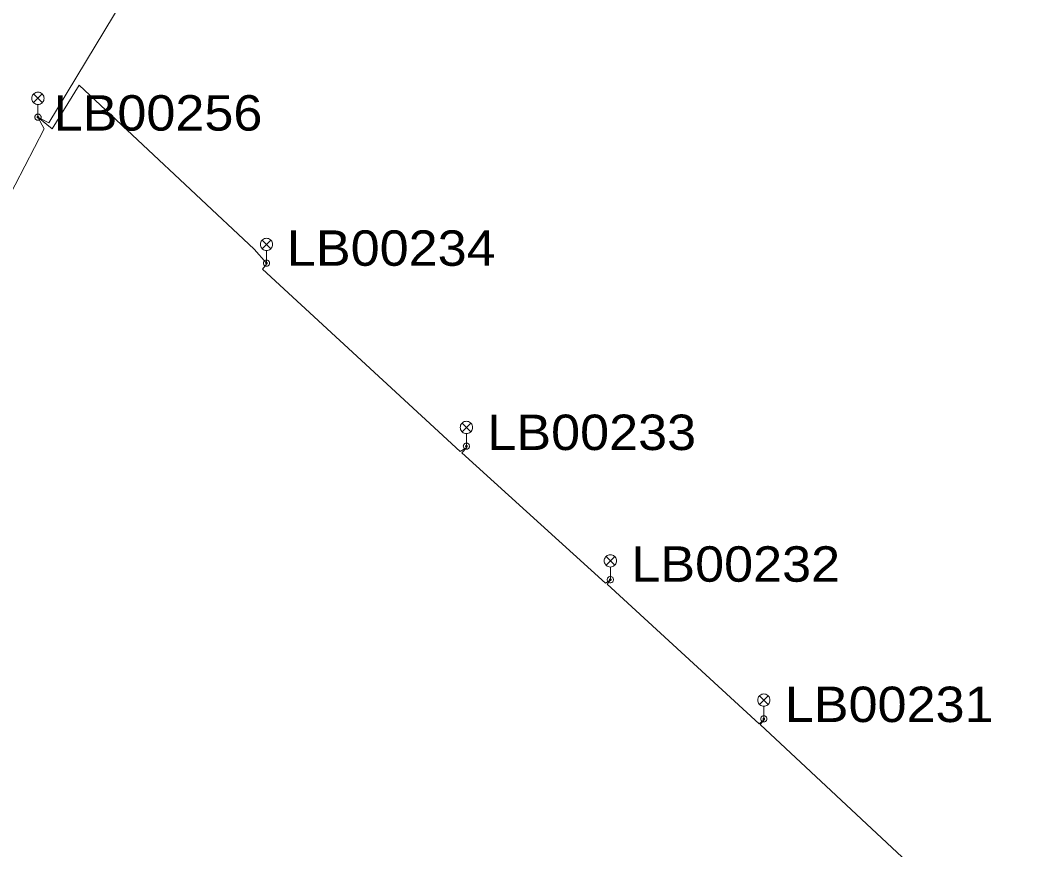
# Model space of a CAD drawing. Extents: x -688049 to -687261, y -973611 to -973038.
# Drawn here: x -687914.5 to -687853.2, y -973537 to -973486.2 of the extents above; entities that cross this region are included whole.
import ezdxf

# ---------------------------------------------------------------- set-up
doc = ezdxf.new("R2010")
doc.units = 0
doc.header["$LTSCALE"] = 0.87
doc.layers.add('1', color=7, linetype='Continuous', lineweight=13)

msp = doc.modelspace()

# ---------------------------------------------------------------- linework, layer by layer
at = {"layer": '1'}
for p, q in [((-687913.655, -973490.735), (-687913.125, -973491.265)), ((-687913.655, -973491.265), (-687913.125, -973490.735)), ((-687913.39, -973492.15), (-687913.39, -973491.375)), ((-687899.685, -973499.665), (-687899.155, -973500.195)), ((-687899.685, -973500.195), (-687899.155, -973499.665)), ((-687899.42, -973501.08), (-687899.42, -973500.305)), ((-687887.465, -973510.855), (-687886.935, -973511.385)), ((-687887.465, -973511.385), (-687886.935, -973510.855)), ((-687887.2, -973512.27), (-687887.2, -973511.495)), ((-687878.665, -973519.015), (-687878.135, -973519.545)), ((-687878.665, -973519.545), (-687878.135, -973519.015)), ((-687878.4, -973520.43), (-687878.4, -973519.655)), ((-687869.285, -973527.525), (-687868.755, -973528.055)), ((-687869.285, -973528.055), (-687868.755, -973527.525)), ((-687869.02, -973528.94), (-687869.02, -973528.165))]:
    msp.add_line(p, q, dxfattribs=at)
for points in [[(-687913.39, -973492.15), (-687912.727, -973492.501), (-687897.443, -973467.178), (-687898.272, -973465.715)], [(-687913.39, -973492.15), (-687912.526, -973492.858), (-687910.875, -973490.203), (-687900.181, -973500.219), (-687899.42, -973501.08)], [(-687942.67, -973532.11), (-687942.806, -973531.57), (-687934.841, -973522.602), (-687917.755, -973502.005), (-687913.006, -973492.864), (-687913.39, -973492.15)], [(-687899.42, -973501.13), (-687899.671, -973501.442), (-687887.585, -973512.602), (-687887.167, -973512.344)], [(-687887.167, -973512.344), (-687887.479, -973512.665), (-687878.69, -973520.633), (-687878.4, -973520.43)], [(-687878.4, -973520.43), (-687878.602, -973520.696), (-687869.304, -973529.25), (-687868.985, -973528.975)], [(-687868.985, -973528.975), (-687869.24, -973529.284), (-687853.757, -973543.759), (-687853.18, -973543.18)]]:
    msp.add_lwpolyline(points, dxfattribs=at)
for points in [[(-687913.015, -973491), (-687913.021, -973490.935), (-687913.038, -973490.872), (-687913.065, -973490.812), (-687913.103, -973490.759), (-687913.149, -973490.713), (-687913.202, -973490.675), (-687913.262, -973490.648), (-687913.325, -973490.631), (-687913.39, -973490.625), (-687913.455, -973490.631), (-687913.518, -973490.648), (-687913.578, -973490.675), (-687913.631, -973490.713), (-687913.677, -973490.759), (-687913.715, -973490.812), (-687913.742, -973490.872), (-687913.759, -973490.935), (-687913.765, -973491), (-687913.759, -973491.065), (-687913.742, -973491.128), (-687913.715, -973491.188), (-687913.677, -973491.241), (-687913.631, -973491.287), (-687913.578, -973491.325), (-687913.518, -973491.352), (-687913.455, -973491.369), (-687913.39, -973491.375), (-687913.325, -973491.369), (-687913.262, -973491.352), (-687913.202, -973491.325), (-687913.149, -973491.287), (-687913.103, -973491.241), (-687913.065, -973491.188), (-687913.038, -973491.128), (-687913.021, -973491.065)], [(-687913.2, -973492.15), (-687913.203, -973492.117), (-687913.211, -973492.085), (-687913.225, -973492.055), (-687913.244, -973492.028), (-687913.268, -973492.004), (-687913.295, -973491.985), (-687913.325, -973491.971), (-687913.357, -973491.963), (-687913.39, -973491.96), (-687913.423, -973491.963), (-687913.455, -973491.971), (-687913.485, -973491.985), (-687913.512, -973492.004), (-687913.536, -973492.028), (-687913.555, -973492.055), (-687913.569, -973492.085), (-687913.577, -973492.117), (-687913.58, -973492.15), (-687913.577, -973492.183), (-687913.569, -973492.215), (-687913.555, -973492.245), (-687913.536, -973492.272), (-687913.512, -973492.296), (-687913.485, -973492.315), (-687913.455, -973492.329), (-687913.423, -973492.337), (-687913.39, -973492.34), (-687913.357, -973492.337), (-687913.325, -973492.329), (-687913.295, -973492.315), (-687913.268, -973492.296), (-687913.244, -973492.272), (-687913.225, -973492.245), (-687913.211, -973492.215), (-687913.203, -973492.183)], [(-687913.34, -973492.15), (-687913.341, -973492.141), (-687913.343, -973492.133), (-687913.347, -973492.125), (-687913.352, -973492.118), (-687913.358, -973492.112), (-687913.365, -973492.107), (-687913.373, -973492.103), (-687913.381, -973492.101), (-687913.39, -973492.1), (-687913.399, -973492.101), (-687913.407, -973492.103), (-687913.415, -973492.107), (-687913.422, -973492.112), (-687913.428, -973492.118), (-687913.433, -973492.125), (-687913.437, -973492.133), (-687913.439, -973492.141), (-687913.44, -973492.15), (-687913.439, -973492.159), (-687913.437, -973492.167), (-687913.433, -973492.175), (-687913.428, -973492.182), (-687913.422, -973492.188), (-687913.415, -973492.193), (-687913.407, -973492.197), (-687913.399, -973492.199), (-687913.39, -973492.2), (-687913.381, -973492.199), (-687913.373, -973492.197), (-687913.365, -973492.193), (-687913.358, -973492.188), (-687913.352, -973492.182), (-687913.347, -973492.175), (-687913.343, -973492.167), (-687913.341, -973492.159)], [(-687899.045, -973499.93), (-687899.051, -973499.865), (-687899.068, -973499.802), (-687899.095, -973499.742), (-687899.133, -973499.689), (-687899.179, -973499.643), (-687899.232, -973499.605), (-687899.292, -973499.578), (-687899.355, -973499.561), (-687899.42, -973499.555), (-687899.485, -973499.561), (-687899.548, -973499.578), (-687899.608, -973499.605), (-687899.661, -973499.643), (-687899.707, -973499.689), (-687899.745, -973499.742), (-687899.772, -973499.802), (-687899.789, -973499.865), (-687899.795, -973499.93), (-687899.789, -973499.995), (-687899.772, -973500.058), (-687899.745, -973500.117), (-687899.707, -973500.171), (-687899.661, -973500.217), (-687899.608, -973500.255), (-687899.548, -973500.282), (-687899.485, -973500.299), (-687899.42, -973500.305), (-687899.355, -973500.299), (-687899.292, -973500.282), (-687899.232, -973500.255), (-687899.179, -973500.217), (-687899.133, -973500.171), (-687899.095, -973500.117), (-687899.068, -973500.058), (-687899.051, -973499.995)], [(-687899.23, -973501.08), (-687899.233, -973501.047), (-687899.241, -973501.015), (-687899.255, -973500.985), (-687899.274, -973500.958), (-687899.298, -973500.934), (-687899.325, -973500.915), (-687899.355, -973500.901), (-687899.387, -973500.893), (-687899.42, -973500.89), (-687899.453, -973500.893), (-687899.485, -973500.901), (-687899.515, -973500.915), (-687899.542, -973500.934), (-687899.566, -973500.958), (-687899.585, -973500.985), (-687899.599, -973501.015), (-687899.607, -973501.047), (-687899.61, -973501.08), (-687899.607, -973501.113), (-687899.599, -973501.145), (-687899.585, -973501.175), (-687899.566, -973501.202), (-687899.542, -973501.226), (-687899.515, -973501.245), (-687899.485, -973501.259), (-687899.453, -973501.267), (-687899.42, -973501.27), (-687899.387, -973501.267), (-687899.355, -973501.259), (-687899.325, -973501.245), (-687899.298, -973501.226), (-687899.274, -973501.202), (-687899.255, -973501.175), (-687899.241, -973501.145), (-687899.233, -973501.113)], [(-687899.37, -973501.08), (-687899.371, -973501.071), (-687899.373, -973501.063), (-687899.377, -973501.055), (-687899.382, -973501.048), (-687899.388, -973501.042), (-687899.395, -973501.037), (-687899.403, -973501.033), (-687899.411, -973501.031), (-687899.42, -973501.03), (-687899.429, -973501.031), (-687899.437, -973501.033), (-687899.445, -973501.037), (-687899.452, -973501.042), (-687899.458, -973501.048), (-687899.463, -973501.055), (-687899.467, -973501.063), (-687899.469, -973501.071), (-687899.47, -973501.08), (-687899.469, -973501.089), (-687899.467, -973501.097), (-687899.463, -973501.105), (-687899.458, -973501.112), (-687899.452, -973501.118), (-687899.445, -973501.123), (-687899.437, -973501.127), (-687899.429, -973501.129), (-687899.42, -973501.13), (-687899.411, -973501.129), (-687899.403, -973501.127), (-687899.395, -973501.123), (-687899.388, -973501.118), (-687899.382, -973501.112), (-687899.377, -973501.105), (-687899.373, -973501.097), (-687899.371, -973501.089)], [(-687886.825, -973511.12), (-687886.831, -973511.055), (-687886.848, -973510.992), (-687886.875, -973510.932), (-687886.913, -973510.879), (-687886.959, -973510.833), (-687887.013, -973510.795), (-687887.072, -973510.768), (-687887.135, -973510.751), (-687887.2, -973510.745), (-687887.265, -973510.751), (-687887.328, -973510.768), (-687887.388, -973510.795), (-687887.441, -973510.833), (-687887.487, -973510.879), (-687887.525, -973510.932), (-687887.552, -973510.992), (-687887.569, -973511.055), (-687887.575, -973511.12), (-687887.569, -973511.185), (-687887.552, -973511.248), (-687887.525, -973511.308), (-687887.487, -973511.361), (-687887.441, -973511.407), (-687887.388, -973511.445), (-687887.328, -973511.472), (-687887.265, -973511.489), (-687887.2, -973511.495), (-687887.135, -973511.489), (-687887.072, -973511.472), (-687887.013, -973511.445), (-687886.959, -973511.407), (-687886.913, -973511.361), (-687886.875, -973511.308), (-687886.848, -973511.248), (-687886.831, -973511.185)], [(-687887.01, -973512.27), (-687887.013, -973512.237), (-687887.021, -973512.205), (-687887.035, -973512.175), (-687887.054, -973512.148), (-687887.078, -973512.124), (-687887.105, -973512.105), (-687887.135, -973512.091), (-687887.167, -973512.083), (-687887.2, -973512.08), (-687887.233, -973512.083), (-687887.265, -973512.091), (-687887.295, -973512.105), (-687887.322, -973512.124), (-687887.346, -973512.148), (-687887.365, -973512.175), (-687887.379, -973512.205), (-687887.387, -973512.237), (-687887.39, -973512.27), (-687887.387, -973512.303), (-687887.379, -973512.335), (-687887.365, -973512.365), (-687887.346, -973512.392), (-687887.322, -973512.416), (-687887.295, -973512.435), (-687887.265, -973512.449), (-687887.233, -973512.457), (-687887.2, -973512.46), (-687887.167, -973512.457), (-687887.135, -973512.449), (-687887.105, -973512.435), (-687887.078, -973512.416), (-687887.054, -973512.392), (-687887.035, -973512.365), (-687887.021, -973512.335), (-687887.013, -973512.303)], [(-687887.15, -973512.27), (-687887.151, -973512.261), (-687887.153, -973512.253), (-687887.157, -973512.245), (-687887.162, -973512.238), (-687887.168, -973512.232), (-687887.175, -973512.227), (-687887.183, -973512.223), (-687887.191, -973512.221), (-687887.2, -973512.22), (-687887.209, -973512.221), (-687887.217, -973512.223), (-687887.225, -973512.227), (-687887.232, -973512.232), (-687887.238, -973512.238), (-687887.243, -973512.245), (-687887.247, -973512.253), (-687887.249, -973512.261), (-687887.25, -973512.27), (-687887.249, -973512.279), (-687887.247, -973512.287), (-687887.243, -973512.295), (-687887.238, -973512.302), (-687887.232, -973512.308), (-687887.225, -973512.313), (-687887.217, -973512.317), (-687887.209, -973512.319), (-687887.2, -973512.32), (-687887.191, -973512.319), (-687887.183, -973512.317), (-687887.175, -973512.313), (-687887.168, -973512.308), (-687887.162, -973512.302), (-687887.157, -973512.295), (-687887.153, -973512.287), (-687887.151, -973512.279)], [(-687878.025, -973519.28), (-687878.031, -973519.215), (-687878.048, -973519.152), (-687878.075, -973519.092), (-687878.113, -973519.039), (-687878.159, -973518.993), (-687878.212, -973518.955), (-687878.272, -973518.928), (-687878.335, -973518.911), (-687878.4, -973518.905), (-687878.465, -973518.911), (-687878.528, -973518.928), (-687878.588, -973518.955), (-687878.641, -973518.993), (-687878.687, -973519.039), (-687878.725, -973519.092), (-687878.752, -973519.152), (-687878.769, -973519.215), (-687878.775, -973519.28), (-687878.769, -973519.345), (-687878.752, -973519.408), (-687878.725, -973519.468), (-687878.687, -973519.521), (-687878.641, -973519.567), (-687878.588, -973519.605), (-687878.528, -973519.632), (-687878.465, -973519.649), (-687878.4, -973519.655), (-687878.335, -973519.649), (-687878.272, -973519.632), (-687878.212, -973519.605), (-687878.159, -973519.567), (-687878.113, -973519.521), (-687878.075, -973519.468), (-687878.048, -973519.408), (-687878.031, -973519.345)], [(-687878.21, -973520.43), (-687878.213, -973520.397), (-687878.221, -973520.365), (-687878.235, -973520.335), (-687878.254, -973520.308), (-687878.278, -973520.284), (-687878.305, -973520.265), (-687878.335, -973520.251), (-687878.367, -973520.243), (-687878.4, -973520.24), (-687878.433, -973520.243), (-687878.465, -973520.251), (-687878.495, -973520.265), (-687878.522, -973520.284), (-687878.546, -973520.308), (-687878.565, -973520.335), (-687878.579, -973520.365), (-687878.587, -973520.397), (-687878.59, -973520.43), (-687878.587, -973520.463), (-687878.579, -973520.495), (-687878.565, -973520.525), (-687878.546, -973520.552), (-687878.522, -973520.576), (-687878.495, -973520.595), (-687878.465, -973520.609), (-687878.433, -973520.617), (-687878.4, -973520.62), (-687878.367, -973520.617), (-687878.335, -973520.609), (-687878.305, -973520.595), (-687878.278, -973520.576), (-687878.254, -973520.552), (-687878.235, -973520.525), (-687878.221, -973520.495), (-687878.213, -973520.463)], [(-687878.35, -973520.43), (-687878.351, -973520.421), (-687878.353, -973520.413), (-687878.357, -973520.405), (-687878.362, -973520.398), (-687878.368, -973520.392), (-687878.375, -973520.387), (-687878.383, -973520.383), (-687878.391, -973520.381), (-687878.4, -973520.38), (-687878.409, -973520.381), (-687878.417, -973520.383), (-687878.425, -973520.387), (-687878.432, -973520.392), (-687878.438, -973520.398), (-687878.443, -973520.405), (-687878.447, -973520.413), (-687878.449, -973520.421), (-687878.45, -973520.43), (-687878.449, -973520.439), (-687878.447, -973520.447), (-687878.443, -973520.455), (-687878.438, -973520.462), (-687878.432, -973520.468), (-687878.425, -973520.473), (-687878.417, -973520.477), (-687878.409, -973520.479), (-687878.4, -973520.48), (-687878.391, -973520.479), (-687878.383, -973520.477), (-687878.375, -973520.473), (-687878.368, -973520.468), (-687878.362, -973520.462), (-687878.357, -973520.455), (-687878.353, -973520.447), (-687878.351, -973520.439)], [(-687868.645, -973527.79), (-687868.651, -973527.725), (-687868.668, -973527.662), (-687868.695, -973527.602), (-687868.733, -973527.549), (-687868.779, -973527.503), (-687868.832, -973527.465), (-687868.892, -973527.438), (-687868.955, -973527.421), (-687869.02, -973527.415), (-687869.085, -973527.421), (-687869.148, -973527.438), (-687869.208, -973527.465), (-687869.261, -973527.503), (-687869.307, -973527.549), (-687869.345, -973527.602), (-687869.372, -973527.662), (-687869.389, -973527.725), (-687869.395, -973527.79), (-687869.389, -973527.855), (-687869.372, -973527.918), (-687869.345, -973527.977), (-687869.307, -973528.031), (-687869.261, -973528.077), (-687869.208, -973528.115), (-687869.148, -973528.142), (-687869.085, -973528.159), (-687869.02, -973528.165), (-687868.955, -973528.159), (-687868.892, -973528.142), (-687868.832, -973528.115), (-687868.779, -973528.077), (-687868.733, -973528.031), (-687868.695, -973527.977), (-687868.668, -973527.918), (-687868.651, -973527.855)], [(-687868.83, -973528.94), (-687868.833, -973528.907), (-687868.841, -973528.875), (-687868.855, -973528.845), (-687868.874, -973528.818), (-687868.898, -973528.794), (-687868.925, -973528.775), (-687868.955, -973528.761), (-687868.987, -973528.753), (-687869.02, -973528.75), (-687869.053, -973528.753), (-687869.085, -973528.761), (-687869.115, -973528.775), (-687869.142, -973528.794), (-687869.166, -973528.818), (-687869.185, -973528.845), (-687869.199, -973528.875), (-687869.207, -973528.907), (-687869.21, -973528.94), (-687869.207, -973528.973), (-687869.199, -973529.005), (-687869.185, -973529.035), (-687869.166, -973529.062), (-687869.142, -973529.086), (-687869.115, -973529.105), (-687869.085, -973529.119), (-687869.053, -973529.127), (-687869.02, -973529.13), (-687868.987, -973529.127), (-687868.955, -973529.119), (-687868.925, -973529.105), (-687868.898, -973529.086), (-687868.874, -973529.062), (-687868.855, -973529.035), (-687868.841, -973529.005), (-687868.833, -973528.973)], [(-687868.97, -973528.94), (-687868.971, -973528.931), (-687868.973, -973528.923), (-687868.977, -973528.915), (-687868.982, -973528.908), (-687868.988, -973528.902), (-687868.995, -973528.897), (-687869.003, -973528.893), (-687869.011, -973528.891), (-687869.02, -973528.89), (-687869.029, -973528.891), (-687869.037, -973528.893), (-687869.045, -973528.897), (-687869.052, -973528.902), (-687869.058, -973528.908), (-687869.063, -973528.915), (-687869.067, -973528.923), (-687869.069, -973528.931), (-687869.07, -973528.94), (-687869.069, -973528.949), (-687869.067, -973528.957), (-687869.063, -973528.965), (-687869.058, -973528.972), (-687869.052, -973528.978), (-687869.045, -973528.983), (-687869.037, -973528.987), (-687869.029, -973528.989), (-687869.02, -973528.99), (-687869.011, -973528.989), (-687869.003, -973528.987), (-687868.995, -973528.983), (-687868.988, -973528.978), (-687868.982, -973528.972), (-687868.977, -973528.965), (-687868.973, -973528.957), (-687868.971, -973528.949)]]:
    msp.add_lwpolyline(points, close=True, dxfattribs=at)

# ---------------------------------------------------------------- texts
at = {"layer": '1', "width": 1.1}
for s, p in [('LB00256', (-687912.433, -973492.975)), ('LB00234', (-687898.174, -973501.24)), ('LB00233', (-687885.921, -973512.504)), ('LB00232', (-687877.119, -973520.555)), ('LB00231', (-687867.739, -973529.135))]:
    msp.add_text(s, height=2.167, dxfattribs=at).set_placement(p)

doc.saveas('drawing.dxf')
